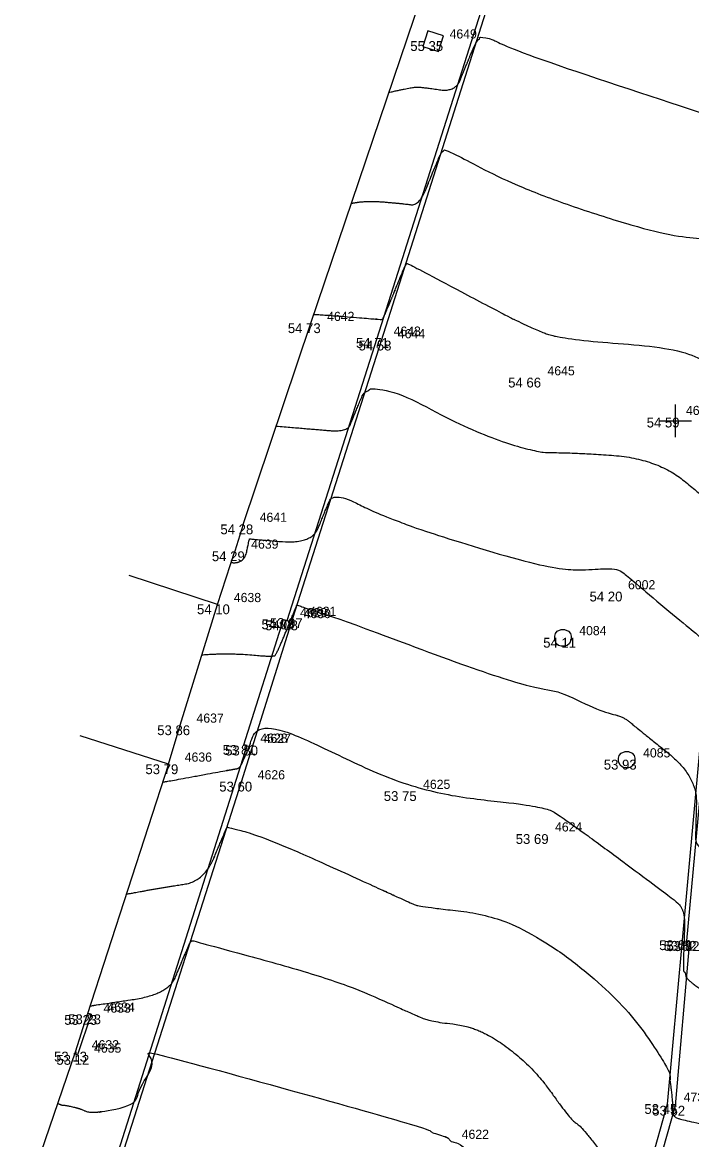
# Model space of a CAD drawing. Extents: x -704017 to -701500, y -1008977 to -1008450.
# Drawn here: x -701719.94 to -701699.5, y -1008871.93 to -1008837.84 of the extents above; entities that cross this region are included whole.
import ezdxf

# ---------------------------------------------------------------- set-up
doc = ezdxf.new("R2010")
doc.units = 0
for name, color, linetype in [('Z_body', 7, 'Continuous'), ('Z_body_cisla', 7, 'Continuous'), ('Z_body_vysky', 7, 'Continuous'), ('Z_budovy', 7, 'Continuous'), ('Z_hekt_sit', 7, 'Continuous'), ('Z_komunikace', 7, 'Continuous'), ('Z_obruby', 7, 'Continuous'), ('Z_rozhrani_ploch', 7, 'Continuous'), ('Z_site_znaky_kanalizace', 7, 'Continuous'), ('Z_site_znaky_vodovod', 7, 'Continuous'), ('Z_vrstevnice_hlavni', 7, 'Continuous'), ('Z_vrstevnice_vedlejsi', 7, 'Continuous'), ('Z_vstupy', 7, 'Continuous')]:
    doc.layers.add(name, color=color, linetype=linetype)

# ---------------------------------------------------------------- blocks, each defined once
blk = doc.blocks.new('POINT_DISPLAY')
blk.add_line((0, 0), (0, 0))
blk = doc.blocks.new('Z620')
for p, q in [((-0.25, 0.05), (-0.23, 0.13)), ((-0.25, -0.05), (-0.25, 0.05)), ((-0.23, 0.13), (-0.17, 0.2)), ((-0.17, 0.2), (-0.05, 0.25)), ((-0.05, 0.25), (0.05, 0.25)), ((0.05, 0.25), (0.17, 0.2)), ((0.17, 0.2), (0.23, 0.13)), ((0.23, 0.13), (0.25, 0.05)), ((0.25, 0.05), (0.25, -0.05)), ((-0.2, -0.17), (-0.25, -0.05)), ((-0.13, -0.23), (-0.2, -0.17)), ((-0.05, -0.25), (-0.13, -0.23)), ((0.05, -0.25), (-0.05, -0.25)), ((0.13, -0.23), (0.05, -0.25)), ((0.2, -0.17), (0.13, -0.23)), ((0.25, -0.05), (0.2, -0.17))]:
    blk.add_line(p, q)
blk = doc.blocks.new('Z608')
for p, q in [((0.25, 0.25), (-0.25, 0.25)), ((-0.25, 0.25), (-0.25, -0.25)), ((0.25, -0.25), (0.25, 0.25)), ((-0.25, -0.25), (0.25, -0.25))]:
    blk.add_line(p, q)

msp = doc.modelspace()

# ---------------------------------------------------------------- linework, layer by layer
at = {"layer": 'Z_budovy'}
for p, q in [((-701711.13, -1008847.02), (-701706.59, -1008833.61)), ((-701713.19, -1008853.16), (-701711.13, -1008847.02)), ((-701713.98, -1008855.6), (-701713.45, -1008853.98)), ((-701713.98, -1008855.6), (-701716.68, -1008854.72)), ((-701715.48, -1008860.48), (-701718.17, -1008859.61)), ((-701715.48, -1008860.48), (-701717.96, -1008868.13)), ((-701719.94, -1008873.98), (-701718.32, -1008869.25))]:
    msp.add_line(p, q, dxfattribs=at)
at = {"layer": 'Z_hekt_sit'}
for p, q in [((-701700, -1008849.5), (-701700, -1008850.5)), ((-701700.5, -1008850), (-701699.5, -1008850))]:
    msp.add_line(p, q, dxfattribs=at)
at = {"layer": 'Z_komunikace'}
for p, q in [((-701708.97, -1008847.55), (-701704.48, -1008833.44)), ((-701711.68, -1008856.02), (-701708.97, -1008847.55)), ((-701698.55, -1008852.28), (-701699.79, -1008865.85)), ((-701713.25, -1008861.01), (-701711.68, -1008856.02)), ((-701717.76, -1008875.15), (-701713.25, -1008861.01)), ((-701699.79, -1008865.85), (-701700.24, -1008870.85)), ((-701700.24, -1008870.85), (-701702.91, -1008880.26))]:
    msp.add_line(p, q, dxfattribs=at)
at = {"layer": 'Z_obruby'}
for p, q in [((-701709.1, -1008847.47), (-701704.64, -1008833.43)), ((-701711.85, -1008856.09), (-701709.1, -1008847.47)), ((-701698.4, -1008852.26), (-701699.65, -1008865.87)), ((-701713.17, -1008859.89), (-701711.96, -1008856.06)), ((-701711.96, -1008856.06), (-701711.85, -1008856.09)), ((-701717.9, -1008875.09), (-701713.07, -1008859.91)), ((-701713.07, -1008859.91), (-701713.17, -1008859.89)), ((-701699.56, -1008865.88), (-701700, -1008870.9)), ((-701699.65, -1008865.87), (-701699.56, -1008865.88)), ((-701700, -1008870.9), (-701702.12, -1008878.4))]:
    msp.add_line(p, q, dxfattribs=at)
at = {"layer": 'Z_rozhrani_ploch'}
for p, q in [((-701717.84, -1008868.11), (-701718.25, -1008869.35)), ((-701717.84, -1008868.11), (-701717.94, -1008868.08)), ((-701718.25, -1008869.35), (-701718.34, -1008869.32))]:
    msp.add_line(p, q, dxfattribs=at)
at = {"layer": 'Z_vrstevnice_hlavni'}
for points in [[(-701709.892, -1008843.363), (-701709.501, -1008843.27), (-701708.325, -1008843.365), (-701707.819, -1008843.439), (-701707.375, -1008842.348), (-701707.121, -1008841.74), (-701706.947, -1008841.731), (-701704.685, -1008842.941), (-701700.39, -1008844.354), (-701698.524, -1008844.475), (-701697.895, -1008845.012), (-701697.91, -1008846.091), (-701697.931, -1008847.042), (-701696.936, -1008847.624), (-701696.008, -1008847.943), (-701695.896, -1008848.045)], [(-701714.455, -1008857.138), (-701713.701, -1008857.079), (-701712.319, -1008857.195), (-701712.277, -1008857.16), (-701712.199, -1008857.181), (-701711.726, -1008856.039), (-701711.575, -1008855.673), (-701711.547, -1008855.603), (-701711.363, -1008855.701), (-701709.912, -1008856.149), (-701704.888, -1008858.05), (-701703.624, -1008858.189), (-701702.238, -1008858.893), (-701701.599, -1008859.01), (-701701.138, -1008859.4), (-701699.332, -1008860.842), (-701699.371, -1008862.425), (-701699.385, -1008862.988), (-701698.803, -1008863.211), (-701698.775, -1008863.334), (-701698.68, -1008863.407), (-701698.627, -1008863.413), (-701697.965, -1008863.82), (-701697.885, -1008863.848), (-701697.881, -1008863.849), (-701697.283, -1008864.103)], [(-701718.86, -1008870.827), (-701718.722, -1008870.891), (-701718.66, -1008870.875), (-701718.15, -1008870.99), (-701717.866, -1008871.139), (-701716.583, -1008870.95), (-701716.35, -1008870.397), (-701715.903, -1008869.328), (-701715.722, -1008869.338), (-701708.062, -1008871.441), (-701707.666, -1008871.622), (-701707.036, -1008871.849), (-701706.979, -1008871.856), (-701706.917, -1008871.902), (-701706.873, -1008871.965), (-701705.991, -1008872.461), (-701702.302, -1008877.715), (-701702.147, -1008877.571), (-701702.37, -1008878.789), (-701702.424, -1008879.118), (-701702.374, -1008879.073), (-701702.332, -1008879.168), (-701701.594, -1008879.84), (-701701.26, -1008880.99)]]:
    msp.add_open_spline(points, degree=2, dxfattribs=at)
at = {"layer": 'Z_vrstevnice_vedlejsi'}
for points in [[(-701707.599, -1008836.59), (-701707.066, -1008836.464), (-701706.275, -1008836.391), (-701705.611, -1008836.488), (-701705.476, -1008836.155), (-701704.92, -1008834.823), (-701704.75, -1008834.815), (-701702.946, -1008835.807), (-701699.028, -1008837.29), (-701696.475, -1008837.686), (-701696.425, -1008837.721), (-701696.647, -1008838.719), (-701696.792, -1008839.361), (-701696.088, -1008840.063), (-701695.259, -1008840.491), (-701694.989, -1008840.679)], [(-701708.745, -1008839.976), (-701707.993, -1008839.799), (-701707.657, -1008839.826), (-701706.715, -1008839.963), (-701706.425, -1008839.251), (-701706.021, -1008838.282), (-701705.743, -1008838.268), (-701704.894, -1008838.722), (-701698.026, -1008840.981), (-701697.546, -1008841.142), (-701697.516, -1008841.162), (-701697.525, -1008841.201), (-701697.548, -1008841.304), (-701697.57, -1008842.799), (-701697.576, -1008843.089), (-701695.827, -1008844.112), (-701695.699, -1008844.156), (-701695.684, -1008844.17)], [(-701711.038, -1008846.749), (-701711.009, -1008846.742), (-701708.993, -1008846.904), (-701708.923, -1008846.914), (-701708.324, -1008845.444), (-701708.222, -1008845.198), (-701708.151, -1008845.195), (-701704.475, -1008847.161), (-701703.339, -1008847.535), (-701699.528, -1008847.783), (-701698.243, -1008848.878), (-701698.25, -1008849.383), (-701698.286, -1008850.995), (-701698.045, -1008851.136), (-701697.243, -1008851.412), (-701696.242, -1008851.899), (-701696.133, -1008852.006)], [(-701712.183, -1008850.158), (-701711.097, -1008850.249), (-701710.017, -1008850.343), (-701709.832, -1008849.896), (-701709.325, -1008848.661), (-701706.088, -1008850.382), (-701704.118, -1008850.99), (-701703.544, -1008850.951), (-701700.578, -1008851.125), (-701698.858, -1008852.546), (-701698.697, -1008852.683), (-701698.594, -1008852.765), (-701698.596, -1008852.854), (-701698.65, -1008854.982), (-701698.06, -1008855.208), (-701697.479, -1008855.653), (-701696.5, -1008855.61), (-701696.742, -1008857.132), (-701696.854, -1008857.956), (-701697.207, -1008859.509), (-701697.182, -1008859.619), (-701697.097, -1008859.686), (-701697.016, -1008859.714)], [(-701713.562, -1008854.321), (-701713.166, -1008854.376), (-701713.006, -1008853.595), (-701712.989, -1008853.6), (-701711.108, -1008853.764), (-701710.704, -1008852.785), (-701710.436, -1008852.132), (-701708.726, -1008853.041), (-701703.677, -1008854.599), (-701702.207, -1008854.5), (-701701.713, -1008854.529), (-701701.426, -1008854.766), (-701699.917, -1008856.041), (-701698.963, -1008856.803), (-701698.984, -1008857.639), (-701699.018, -1008858.985), (-701697.627, -1008859.518), (-701697.559, -1008859.811), (-701697.334, -1008859.987), (-701697.332, -1008859.987), (-701697.306, -1008860.003), (-701697.092, -1008860.077), (-701697.082, -1008860.081), (-701697.059, -1008860.091)], [(-701715.657, -1008861.026), (-701715.649, -1008861.025), (-701713.488, -1008860.629), (-701713.29, -1008860.6), (-701713.115, -1008860.185), (-701712.614, -1008858.987), (-701708.2, -1008861.3), (-701704.064, -1008861.754), (-701703.498, -1008862.043), (-701700.212, -1008864.473), (-701699.701, -1008864.881), (-701699.725, -1008865.859), (-701699.762, -1008866.812), (-701699.689, -1008866.82), (-701699.663, -1008867.051), (-701698.857, -1008867.562), (-701698.15, -1008867.665), (-701697.535, -1008867.905)], [(-701716.764, -1008864.442), (-701716.702, -1008864.431), (-701715.581, -1008864.226), (-701714.387, -1008864.05), (-701713.767, -1008862.574), (-701713.692, -1008862.396), (-701713.662, -1008862.398), (-701712.385, -1008862.748), (-701708.022, -1008864.741), (-701707.812, -1008864.816), (-701704.944, -1008865.156), (-701701.752, -1008867.517), (-701700.146, -1008869.808), (-701700.16, -1008870.177), (-701700.148, -1008870.178), (-701700.069, -1008870.886), (-701700.092, -1008871.226), (-701699.741, -1008871.343), (-701697.848, -1008871.757)], [(-701717.871, -1008867.857), (-701717.756, -1008867.838), (-701717.673, -1008867.822), (-701715.485, -1008867.5), (-701715.058, -1008866.486), (-701714.798, -1008865.862), (-701714.692, -1008865.868), (-701710.224, -1008867.095), (-701707.844, -1008868.181), (-701707.424, -1008868.333), (-701705.961, -1008868.506), (-701704.335, -1008869.709), (-701703.188, -1008871.346), (-701702.796, -1008871.566), (-701701.156, -1008873.901), (-701701.088, -1008873.837), (-701701.23, -1008874.615), (-701701.204, -1008874.722), (-701701.244, -1008875.302), (-701699.632, -1008875.838), (-701698.821, -1008877.113), (-701698.653, -1008877.266), (-701698.355, -1008877.477)]]:
    msp.add_open_spline(points, degree=2, dxfattribs=at)
at = {"layer": 'Z_vstupy'}
for p, q in [((-701713.19, -1008853.16), (-701713.45, -1008853.98)), ((-701715.12, -1008859.29), (-701713.98, -1008855.6)), ((-701715.48, -1008860.48), (-701715.12, -1008859.29)), ((-701718.32, -1008869.25), (-701717.96, -1008868.13))]:
    msp.add_line(p, q, dxfattribs=at)

# ---------------------------------------------------------------- block references
at = {"layer": 'Z_body'}
for p in [(-701707.39, -1008838.41), (-701711.13, -1008847.02), (-701709.1, -1008847.47), (-701708.97, -1008847.55), (-701704.4, -1008848.68), (-701700.17, -1008849.9), (-701713.19, -1008853.16), (-701713.45, -1008853.98), (-701701.94, -1008855.21), (-701713.98, -1008855.6), (-701711.96, -1008856.06), (-701711.85, -1008856.09), (-701711.68, -1008856.02), (-701703.43, -1008856.62), (-701715.12, -1008859.29), (-701713.17, -1008859.89), (-701713.07, -1008859.91), (-701701.48, -1008860.34), (-701715.48, -1008860.48), (-701713.25, -1008861.01), (-701708.2, -1008861.3), (-701704.17, -1008862.61), (-701699.79, -1008865.85), (-701699.65, -1008865.87), (-701699.56, -1008865.88), (-701717.96, -1008868.13), (-701717.84, -1008868.11), (-701718.32, -1008869.25), (-701718.25, -1008869.35), (-701700.24, -1008870.85), (-701700, -1008870.9)]:
    msp.add_blockref('POINT_DISPLAY', p, dxfattribs=at)
at = {"layer": 'Z_site_znaky_kanalizace'}
for p in [(-701703.43, -1008856.62), (-701701.48, -1008860.34)]:
    msp.add_blockref('Z620', p, dxfattribs=at)
at = {"layer": 'Z_site_znaky_vodovod', "rotation": -18.000000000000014}
msp.add_blockref('Z608', (-701707.39, -1008838.41), dxfattribs=at)

# ---------------------------------------------------------------- texts
at = {"layer": 'Z_body_cisla'}
for s, p in [('4649', (-701706.89, -1008838.33)), ('4642', (-701710.63, -1008846.95)), ('4643', (-701708.6, -1008847.4)), ('4644', (-701708.47, -1008847.48)), ('4645', (-701703.9, -1008848.61)), ('4646', (-701699.67, -1008849.82)), ('4641', (-701712.69, -1008853.08)), ('4639', (-701712.95, -1008853.9)), ('6002', (-701701.44, -1008855.14)), ('4638', (-701713.48, -1008855.53)), ('4629', (-701711.46, -1008855.99)), ('4630', (-701711.35, -1008856.02)), ('4631', (-701711.18, -1008855.95)), ('4084', (-701702.93, -1008856.54)), ('4637', (-701714.62, -1008859.21)), ('4628', (-701712.67, -1008859.82)), ('4627', (-701712.57, -1008859.83)), ('4085', (-701700.98, -1008860.27)), ('4636', (-701714.98, -1008860.4)), ('4626', (-701712.75, -1008860.94)), ('4625', (-701707.7, -1008861.23)), ('4624', (-701703.67, -1008862.53)), ('4633', (-701717.46, -1008868.06)), ('4634', (-701717.34, -1008868.03)), ('4632', (-701717.82, -1008869.18)), ('4635', (-701717.75, -1008869.28)), ('4730', (-701699.74, -1008870.78)), ('4622', (-701706.52, -1008871.91))]:
    msp.add_text(s, height=0.28, dxfattribs=at).set_placement(p)
at = {"layer": 'Z_body_vysky'}
for s, p in [('55 35', (-701708.09, -1008838.71)), ('54 73', (-701711.83, -1008847.32)), ('54 71', (-701709.75, -1008847.77)), ('54 58', (-701709.67, -1008847.85)), ('54 66', (-701705.1, -1008848.98)), ('54 59', (-701700.87, -1008850.2)), ('54 28', (-701713.89, -1008853.46)), ('54 29', (-701714.15, -1008854.28)), ('54 20', (-701702.615, -1008855.51)), ('54 10', (-701714.605, -1008855.9)), ('54 08', (-701712.635, -1008856.36)), ('54 08', (-701712.525, -1008856.39)), ('53 97', (-701712.38, -1008856.32)), ('54 11', (-701704.03, -1008856.92)), ('53 86', (-701715.82, -1008859.59)), ('53 81', (-701713.82, -1008860.19)), ('53 80', (-701713.745, -1008860.21)), ('53 93', (-701702.18, -1008860.64)), ('53 79', (-701716.18, -1008860.78)), ('53 60', (-701713.925, -1008861.31)), ('53 75', (-701708.9, -1008861.6)), ('53 69', (-701704.87, -1008862.91)), ('53 69', (-701700.49, -1008866.15)), ('53 82', (-701700.35, -1008866.17)), ('53 82', (-701700.26, -1008866.18)), ('53 23', (-701718.66, -1008868.43)), ('53 23', (-701718.54, -1008868.41)), ('53 13', (-701718.97, -1008869.55)), ('53 12', (-701718.9, -1008869.65)), ('53 45', (-701700.94, -1008871.15)), ('53 52', (-701700.7, -1008871.2))]:
    msp.add_text(s, height=0.3, dxfattribs=at).set_placement(p)

doc.saveas('drawing.dxf')
